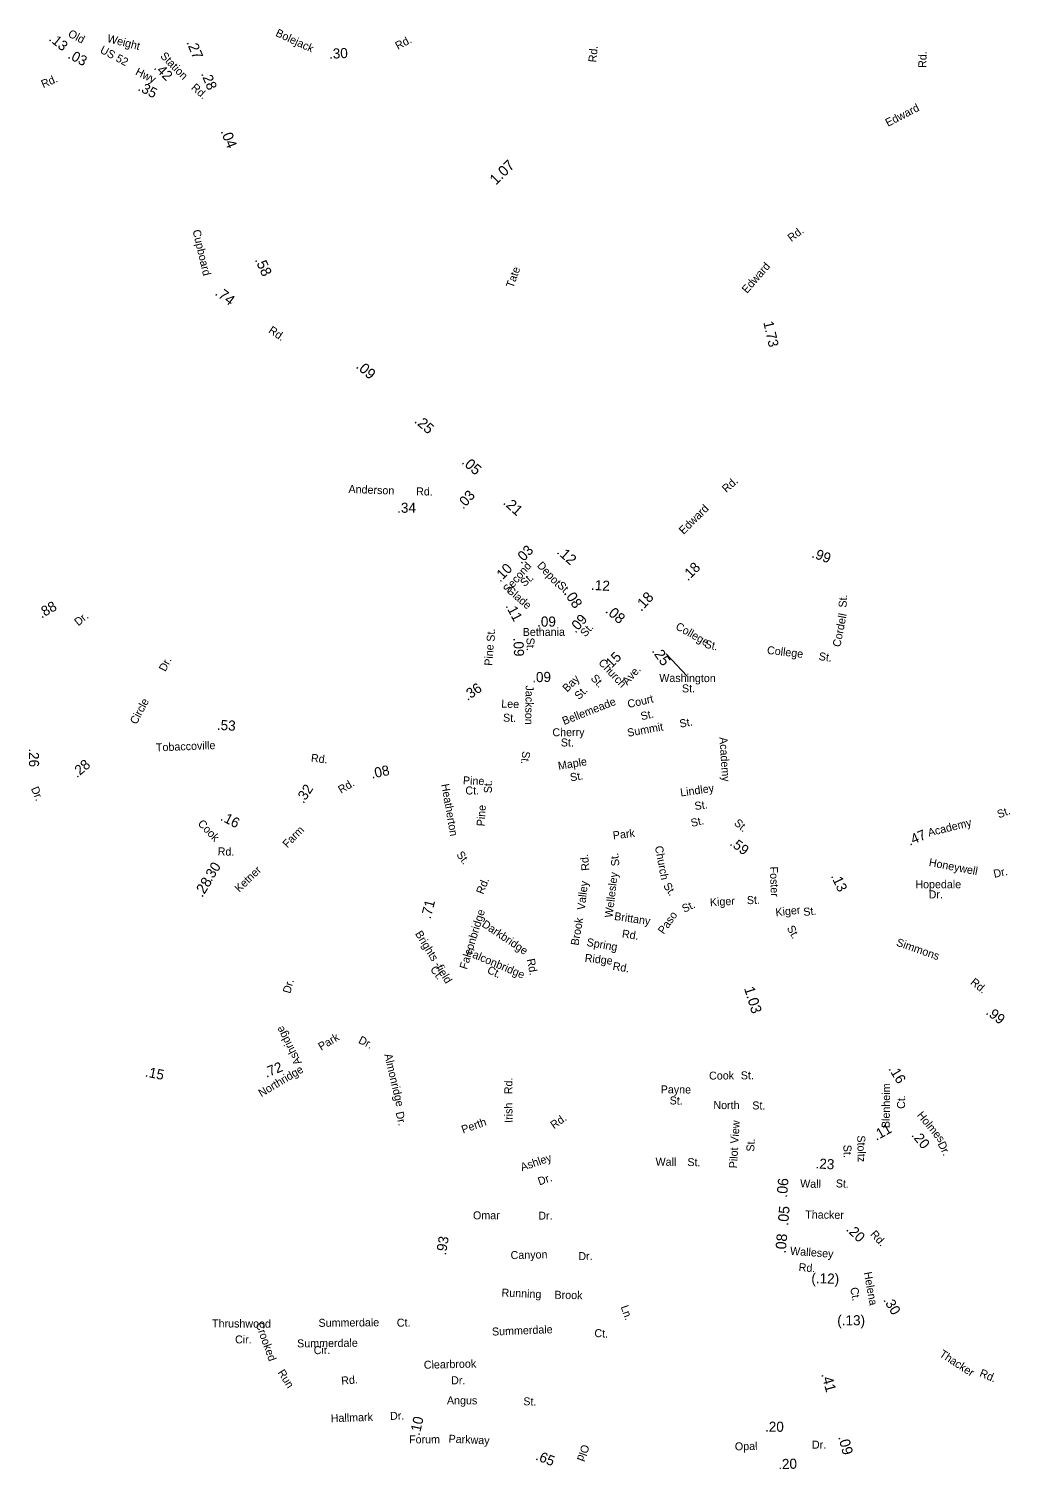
# Model space of a CAD drawing. Extents: x 1553981 to 1780076, y 812965 to 996873.
# Drawn here: x 1611607 to 1623259, y 899058 to 916160 of the extents above; entities that cross this region are included whole.
import ezdxf

# ---------------------------------------------------------------- set-up
doc = ezdxf.new("R2010")
doc.units = 0
for name, color, linetype in [('Exist Road Non-System Type 51 Label', 7, 'Continuous'), ('Exist Road Primary NC Service Mileage Hundredths English Label', 7, 'Continuous'), ('Exist Road Secondary Mileage Hundredths English Label', 7, 'Continuous'), ('Map Preparation Border Antique Large Shape', 7, 'Continuous')]:
    doc.layers.add(name, color=color, linetype=linetype)

msp = doc.modelspace()

# ---------------------------------------------------------------- linework, layer by layer
at = {"layer": 'Exist Road Non-System Type 51 Label'}
msp.add_lwpolyline([(1619173, 908741), (1619423, 908476)], dxfattribs=at)

# ---------------------------------------------------------------- texts
for s, rotation, p in [('Depot', 313.0043, (1617634, 909782)), ('St.', 314.4276, (1617874, 909545)), ('St.', 86.7449, (1621315, 909286)), ('Cordell', 78.9341, (1621242, 908815)), ('St.', 88.704, (1617138, 908882)), ('College', 330.4152, (1619277, 909038)), ('Pine', 86.1804, (1617110, 908595)), ('St.', 347.1512, (1619625, 908814)), ('College', 353.4808, (1620368, 908739)), ('Church', 313.1543, (1618363, 908628)), ('St.', 352.2827, (1620982, 908666)), ('Bay', 44.7999, (1617998, 908278)), ('St.', 313.1543, (1618272, 908443)), ('Ave.', 48.2454, (1618712, 908361)), ('Washington', 359.7339, (1619092, 908406)), ('Jackson', 269.2198, (1617506, 908364)), ('St.', 44.7999, (1618140, 908188)), ('St.', 0.2268, (1619362, 908281)), ('Lee', 357.9044, (1617215, 908102)), ('Bellemeade', 21.3693, (1617962, 907893)), ('Court', 12.6952, (1618726, 908095)), ('St.', 357.9044, (1617236, 907935)), ('St.', 12.6952, (1618882, 907950)), ('St.', 9.9072, (1619341, 907862)), ('Cherry', 0.4515, (1617824, 907760)), ('Summit', 10.2169, (1618721, 907754)), ('St.', 359.302, (1617923, 907640)), ('St.', 263.1054, (1617468, 907588)), ('Maple', 9.4837, (1617898, 907361)), ('Pine', 357.9687, (1616760, 907190)), ('St.', 9.4837, (1618041, 907224)), ('Heatherton', 279.9144, (1616503, 907188)), ('Ct.', 0.0702, (1616790, 907069)), ('St.', 88.704, (1617104, 907083)), ('Lindley', 8.0181, (1619348, 907045)), ('Pine', 86.1804, (1617017, 906689)), ('St.', 8.0092, (1619518, 906884)), ('St.', 12.7917, (1619478, 906683)), ('Park', 7.0393, (1618547, 906535)), ('Church', 280.4137, (1619040, 906451)), ('St.', 306.3077, (1616679, 906354)), ('Rd.', 95.6977, (1618265, 906168)), ('St.', 96.0298, (1618620, 906223)), ('Honeywell', 349.1792, (1622288, 906221)), ('Wellesley', 83.1258, (1618537, 905602)), ('Foster', 272.1215, (1620405, 906212)), ('Dr.', 12.4372, (1623071, 906079)), ('Rd.', 68.2472, (1617002, 905877)), ('Valley', 83.413, (1618208, 905693)), ('St.', 303.7459, (1619135, 905985)), ('Hopedale', 359.9933, (1622133, 905956)), ('Dr.', 0.3054, (1622291, 905835)), ('St.', 25.0303, (1619388, 905664)), ('Kiger', 3.2858, (1619696, 905742)), ('St.', 2.2978, (1620134, 905766)), ('Falconbridge', 72.81, (1616808, 904986)), ('Darkbridge', 326.0203, (1616977, 905508)), ('Brook', 80.2186, (1618133, 905271)), ('Brittany', 351.7451, (1618553, 905580)), ('Paso', 54.5401, (1619145, 905403)), ('Kiger', 6.1203, (1620477, 905622)), ('St.', 6.1203, (1620808, 905626)), ('Brights -field', 301.6463, (1616189, 905416)), ('Rd.', 351.7451, (1618645, 905372)), ('St.', 298.4184, (1620604, 905484)), ('Falconbridge', 337.0718, (1616794, 905165)), ('Spring', 350.2233, (1618225, 905272)), ('Rd.', 281.3645, (1617519, 905111)), ('Ridge', 353.8249, (1618204, 905083)), ('Rd.', 350.0772, (1618534, 904989)), ('Ct.', 306.2767, (1616368, 904992)), ('Ct.', 334.7485, (1617040, 904954)), ('Dr.', 74.2178, (1614710, 904700)), ('Ashridge', 117.3404, (1614850, 903886)), ('Almonridge', 283.2611, (1615826, 903981)), ('Rd.', 89.3522, (1617347, 903510)), ('Cook', 0.5505, (1619684, 903683)), ('St.', 1.0714, (1620061, 903686)), ('Payne', 359.5513, (1619109, 903521)), ('Irish', 90.7296, (1617351, 903171)), ('St.', 358.3709, (1619214, 903390)), ('North', 359.8416, (1619735, 903334)), ('St.', 359.3198, (1620196, 903330)), ('Dr.', 283.2611, (1615961, 903293)), ('Perth', 19.5353, (1616763, 903042)), ('Rd.', 35.5755, (1617842, 903093)), ('View', 85.9709, (1620030, 902921)), ('Pilot', 87.0253, (1620016, 902629)), ('St.', 87.0253, (1620220, 902827)), ('Ashley', 18.9451, (1617463, 902596)), ('Wall', 359.684, (1619048, 902661)), ('St.', 358.9513, (1619425, 902658)), ('Dr.', 18.9451, (1617669, 902427)), ('Omar', 0.3586, (1616881, 902024)), ('Dr.', 359.8614, (1617656, 902021)), ('Canyon', 1.2925, (1617328, 901552)), ('Dr.', 0.6867, (1618132, 901540)), ('Running', 357.6472, (1617218, 901108)), ('Brook', 358.8813, (1617848, 901082)), ('Ln.', 289.3625, (1618633, 900986)), ('Thrushwood', 359.6785, (1613782, 900742)), ('Crooked', 289.7016, (1614298, 900783)), ('Summerdale', 0.5753, (1615047, 900748)), ('Ct.', 1.3393, (1615977, 900749)), ('Cir.', 359.5835, (1614055, 900552)), ('Summerdale', 0.5753, (1614793, 900504)), ('Summerdale', 2.3336, (1617108, 900644)), ('Ct.', 357.1896, (1618320, 900628)), ('Cir.', 1.3393, (1614990, 900423)), ('Thacker', 326.8566, (1622410, 900404)), ('Clearbrook', 1.4178, (1616298, 900250)), ('Run', 302.7749, (1614557, 900205)), ('Rd.', 4.8703, (1615320, 900061)), ('Dr.', 359.3266, (1616620, 900067)), ('Rd.', 336.7112, (1622887, 900165)), ('Angus', 359.8941, (1616571, 899828)), ('St.', 358.8357, (1617477, 899817)), ('Hallmark', 1.9638, (1615193, 899615)), ('Dr.', 1.7277, (1615897, 899643)), ('Old', 250.3182, (1618178, 899360))]:
    msp.add_text(s, height=95, rotation=rotation, dxfattribs=at).set_placement(p)
at = {"layer": 'Exist Road Primary NC Service Mileage Hundredths English Label'}
for s, rotation, p in [('.27', 292.6199, (1613476, 916001)), ('.04', 291.7778, (1613882, 914944)), ('.58', 294.6468, (1614288, 913419)), ('.09', 318.8745, (1615482, 912141)), ('.25', 318.8745, (1616176, 911493)), ('.05', 318.8745, (1616738, 911005)), ('.21', 317.9085, (1617229, 910525)), ('.12', 318.3274, (1617867, 909938)), ('.08', 303.9069, (1617955, 909458)), ('.18', 47.2193, (1618878, 909234)), ('.08', 319.1979, (1618444, 909238)), ('.25', 305.1418, (1618999, 908774)), ('1.03', 287.3387, (1620098, 904767)), ('.06', 85.1469, (1620609, 902278)), ('.05', 85.1469, (1620622, 901946)), ('.08', 84.947, (1620593, 901618)), ('.41', 285.2863, (1621015, 900186)), ('.09', 284.9866, (1621216, 899441))]:
    msp.add_text(s, height=125, rotation=rotation, dxfattribs=at).set_placement(p)
at = {"layer": 'Exist Road Secondary Mileage Hundredths English Label'}
for s, height, rotation, p in [('.13', 120, 320.8792, (1611836, 916029)), ('.03', 120, 332.7094, (1612061, 915816)), ('.30', 120, 2.7224, (1615174, 915804)), ('.42', 120, 315.3122, (1613084, 915690)), ('.35', 120, 332.417, (1612893, 915435)), ('.28', 120, 292.536, (1613650, 915627)), ('1.07', 125, 44.3494, (1617152, 914300)), ('.74', 125, 322.9183, (1613808, 913008)), ('1.73', 120, 282.7937, (1620327, 912676)), ('.03', 120, 48.1457, (1616765, 910449)), ('.03', 120, 46.1907, (1617453, 909799)), ('.99', 120, 340.0908, (1620894, 909888)), ('.10', 120, 46.1494, (1617203, 909582)), ('.18', 120, 45.38, (1619433, 909597)), ('.12', 120, 356.5999, (1618280, 909499)), ('.88', 120, 29.9847, (1611758, 909157)), ('.11', 120, 297.6042, (1617265, 909309)), ('.09', 120, 0.1597, (1617642, 909062)), ('.09', 120, 48.3512, (1618098, 908977)), ('.09', 120, 272.5317, (1617359, 908928)), ('.15', 120, 45.7586, (1618497, 908532)), ('.09', 120, 1.0195, (1617585, 908402)), ('.36', 120, 34.6148, (1616815, 908178)), ('.53', 120, 356.9888, (1613837, 907837)), ('.26', 120, 270.4346, (1611607, 907617)), ('.28', 120, 40.5545, (1612179, 907261)), ('.08', 120, 11.7466, (1615680, 907257)), ('.32', 120, 56.7412, (1614867, 906954)), ('.16', 120, 332.3883, (1613873, 906769)), ('.47', 120, 23.0213, (1622067, 906459)), ('.59', 120, 323.2484, (1619921, 906474)), ('.30', 120, 58.1349, (1613775, 906028)), ('.28', 125, 58.1496, (1613666, 905839)), ('.13', 120, 295.3248, (1621127, 906102)), ('.71', 120, 75.7821, (1616377, 905585)), ('.99', 120, 322.5068, (1622962, 904468)), ('.72', 120, 22.2615, (1614427, 903705)), ('.15', 120, 348.6815, (1612981, 903722)), ('.16', 120, 301.1679, (1621810, 903813)), ('.11', 120, 28.9038, (1621669, 902956)), ('.20', 120, 309.6216, (1622080, 903021)), ('.23', 120, 356.7055, (1620945, 902630)), ('.93', 120, 80.4815, (1616558, 901594)), ('.20', 120, 315.6944, (1621304, 901898)), ('(.12)', 120, 358.3427, (1620897, 901268)), ('.30', 120, 300.932, (1621748, 901068)), ('(.13)', 120, 0.1229, (1621206, 900766)), ('.10', 120, 77.2771, (1616246, 899451)), ('.20', 120, 359.8371, (1620348, 899503)), ('.65', 120, 338.1831, (1617615, 899174)), ('.20', 120, 1.6349, (1620506, 899058))]:
    msp.add_text(s, height=height, rotation=rotation, dxfattribs=at).set_placement(p)
msp.add_text('.34', height=120, dxfattribs=at).set_placement((1615980, 910414))
at = {"layer": 'Map Preparation Border Antique Large Shape'}
for s, rotation, p in [('Old', 332.6936, (1612064, 916073)), ('Weight', 345.5874, (1612530, 916005)), ('Bolejack', 335.0642, (1614528, 916079)), ('Rd.', 28.0517, (1615989, 915909)), ('US 52', 331.7522, (1612444, 915882)), ('Station', 314.4463, (1613161, 915830)), ('Rd.', 84.5497, (1618344, 915759)), ('Rd.', 88.4325, (1622262, 915695)), ('Hwy', 333.9445, (1612864, 915619)), ('Rd.', 23.3282, (1611778, 915455)), ('Rd.', 318.2951, (1613527, 915451)), ('Edward', 27.0714, (1621807, 914996)), ('Rd.', 37.2081, (1620661, 913627)), ('Cupboard', 283.3108, (1613550, 913764)), ('Tate', 70.2999, (1617358, 913076)), ('Edward', 48.8877, (1620134, 913012)), ('Rd.', 325.8251, (1614444, 912560)), ('Anderson', 357.8118, (1615401, 910650)), ('Rd.', 359.3705, (1616205, 910621)), ('Rd.', 41.8021, (1619889, 910647)), ('Edward', 44.8802, (1619382, 910151)), ('Second', 49.2735, (1617300, 909453)), ('Glade', 319.1843, (1617268, 909483)), ('St.', 41.3102, (1617492, 909530)), ('Dr.', 39.698, (1612195, 909065)), ('Bethania', 0.2473, (1617471, 908951)), ('St.', 48.3512, (1618215, 908933)), ('St.', 271.6699, (1617515, 908930)), ('Dr.', 63.0951, (1613229, 908521)), ('Circle', 61.9976, (1612885, 907893)), ('Tobaccoville', 2.2913, (1613118, 907580)), ('Academy', 273.6939, (1619806, 907748)), ('Rd.', 353.5275, (1614953, 907459)), ('Dr.', 292.6804, (1611630, 907140)), ('Rd.', 31.4011, (1615315, 907076)), ('St.', 319.5527, (1619973, 906718)), ('Academy', 13.8956, (1622294, 906569)), ('St.', 20.5831, (1623125, 906785)), ('Cook', 313.6186, (1613606, 906717)), ('Farm', 45.4357, (1614676, 906428)), ('Rd.', 358.3672, (1613848, 906347)), ('Ketner', 44.1665, (1614106, 905901)), ('Simmons', 340.6391, (1621899, 905276)), ('Rd.', 320.6935, (1622779, 904826)), ('Park', 31.0484, (1615078, 904026)), ('Dr.', 333.1158, (1615512, 904123)), ('Northridge', 31.0759, (1614368, 903473)), ('Blenheim', 89.3428, (1621828, 903108)), ('Ct.', 89.3428, (1622010, 903336)), ('Holmes', 309.6216, (1622147, 903259)), ('Stoltz', 271.1444, (1621443, 903021)), ('St.', 271.1444, (1621279, 902910)), ('Dr.', 295.7488, (1622396, 902922)), ('Wall', 358.2844, (1620764, 902404)), ('St.', 357.5467, (1621187, 902405)), ('Thacker', 359.3278, (1620825, 902035)), ('Rd.', 312.972, (1621591, 901841)), ('Wallesey', 355.7914, (1620643, 901605)), ('Rd.', 355.7914, (1620745, 901411)), ('Helena', 280.271, (1621520, 901393)), ('Ct.', 280.271, (1621359, 901209)), ('Forum', 0.2032, (1616122, 899364)), ('Parkway', 357.4848, (1616589, 899373)), ('Opal', 1.2662, (1619991, 899281)), ('Dr.', 359.8371, (1620905, 899302))]:
    msp.add_text(s, height=95, rotation=rotation, dxfattribs=at).set_placement(p)

doc.saveas('drawing.dxf')
